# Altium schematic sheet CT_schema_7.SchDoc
size 274 x 160 mm
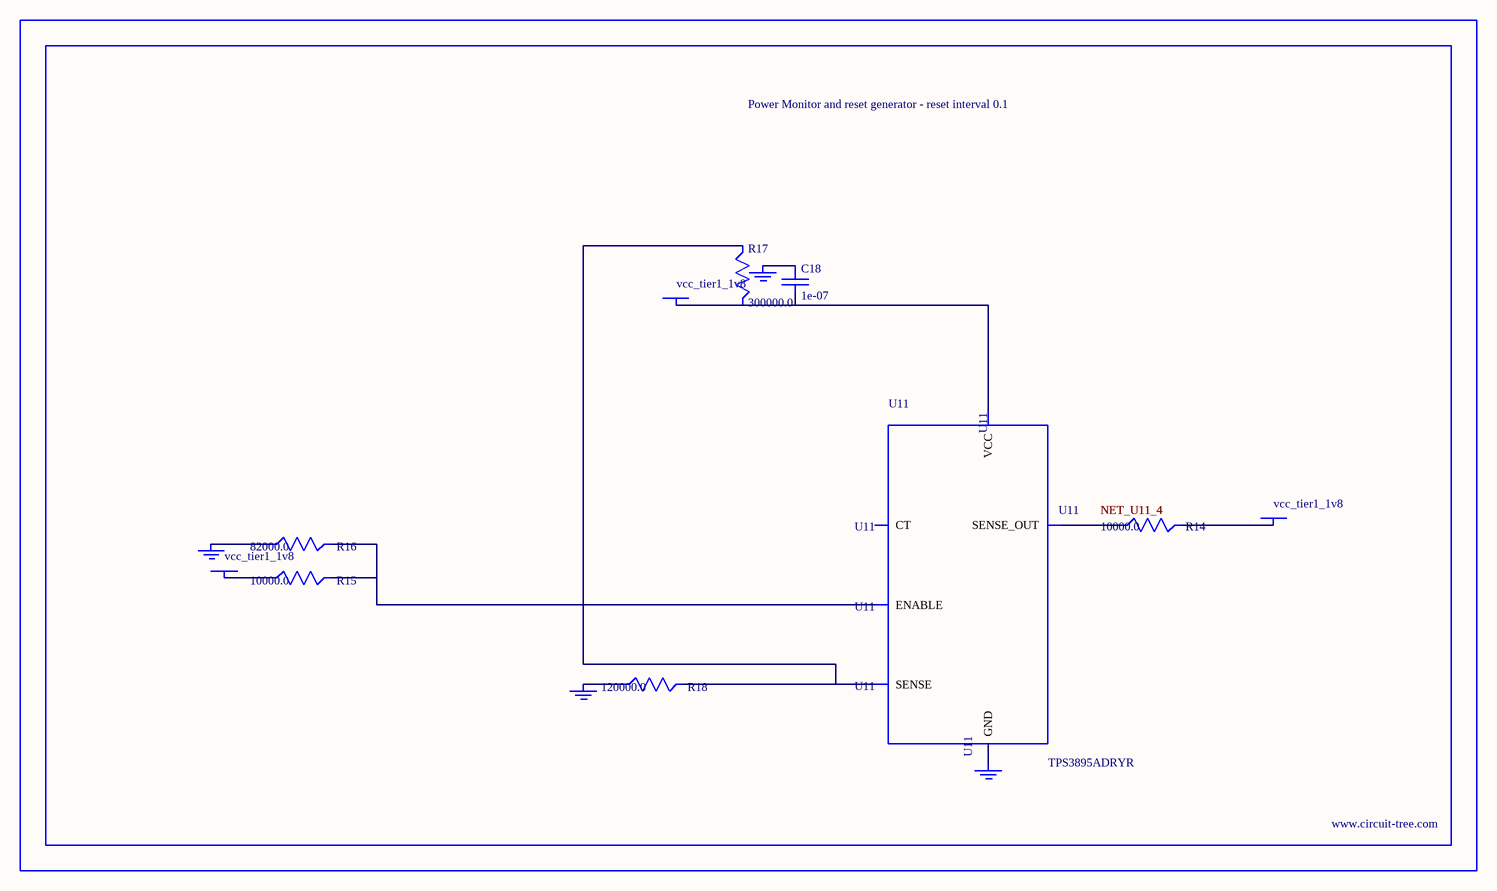
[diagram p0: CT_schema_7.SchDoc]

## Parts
BORDER6  (no value)
C18  1e-07  [C0402]
GND_INSTANCE_6_0  (no value)
GND_INSTANCE_6_1  (no value)
GND_INSTANCE_6_2  (no value)
GND_INSTANCE_6_3  (no value)
POWER_INSTANCE_6_0  vcc_tier1_1v8
POWER_INSTANCE_6_1  vcc_tier1_1v8
POWER_INSTANCE_6_2  vcc_tier1_1v8
R14  10000.0  [R0603]
R15  10000.0  [R0603]
R16  82000.0  [R0603]
R17  300000.0  [R0603]
R18  120000.0  [R0603]
U11  TPS3895ADRYR  [SON-6]

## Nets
NetC18_1: C18.1 GND_INSTANCE_6_2.0(GND)
NetC18_2: C18.2 POWER_INSTANCE_6_2.0(PWR) R17.2 U11.6(VCC)
NetGND_INSTANCE_6_0_0: GND_INSTANCE_6_0.0(GND) R16.1
NetGND_INSTANCE_6_1_0: GND_INSTANCE_6_1.0(GND) R18.1
NetGND_INSTANCE_6_3_0: GND_INSTANCE_6_3.0(GND) U11.2(GND)
NetPOWER_INSTANCE_6_0_0: POWER_INSTANCE_6_0.0(PWR) R15.1
NetPOWER_INSTANCE_6_1_0: POWER_INSTANCE_6_1.0(PWR) R14.2
NetR14_1: R14.1 U11.4(SENSE_OUT)
NetR15_2: R15.2 R16.2 U11.1(ENABLE)
NetR17_1: R17.1 R18.2 U11.3(SENSE)

Not connected (* = marked no-connect by the designer): U11 5(CT)

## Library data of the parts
BORDER6 = BORDER_PAGE6
C18 = C0402C104K3RACTU
GND_INSTANCE_6_0-GND_INSTANCE_6_3 = GND
POWER_INSTANCE_6_0-POWER_INSTANCE_6_2 = PWR
R14 R15 = RC0603JR-0710KL
R16 = RC0603JR-0782KL
R17 = RC0603JR-07300KL
R18 = RC0603JR-07120KL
